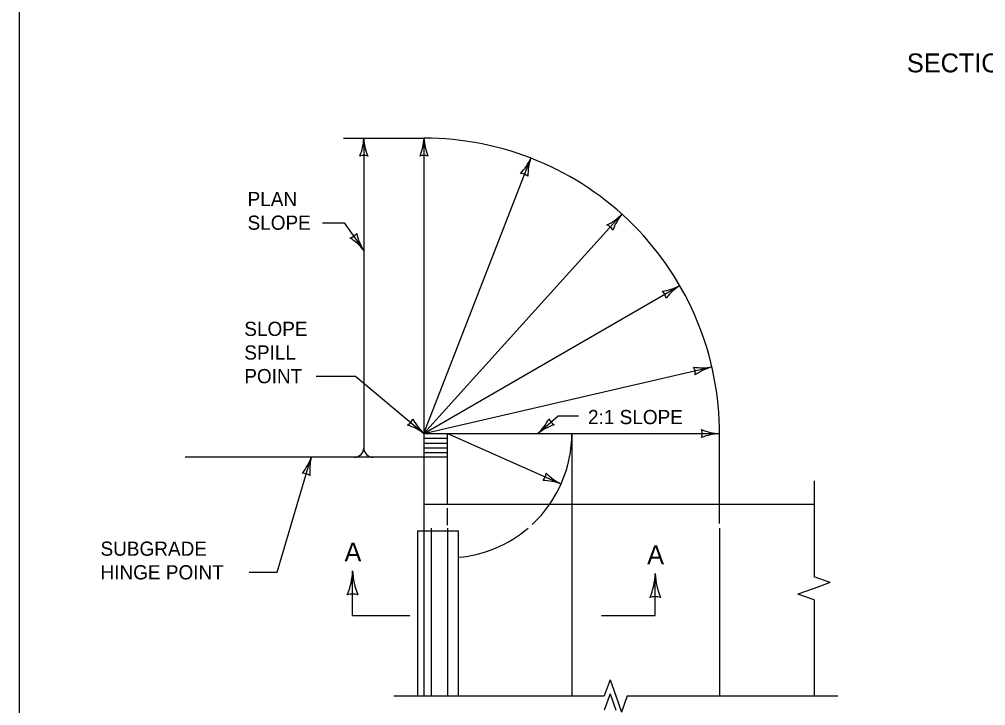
# Model space of a CAD drawing. Extents: x 49991.4 to 50021, y 49987.6 to 50011.4.
# Drawn here: x 50000.336 to 50004.423, y 50005.456 to 50008.359 of the extents above; entities that cross this region are included whole.
import ezdxf

# ---------------------------------------------------------------- set-up
doc = ezdxf.new("R2010")
doc.units = 0
for name, color, linetype in [('Level 1', 7, 'Continuous'), ('Level 2', 7, 'Continuous'), ('Level 3', 7, 'Continuous'), ('Level 4', 7, 'Continuous'), ('Level 6', 7, 'Continuous')]:
    doc.layers.add(name, color=color, linetype=linetype)

msp = doc.modelspace()

# ---------------------------------------------------------------- linework, layer by layer
at = {"layer": 'Level 1'}
for p, q in [((50001.7071, 50007.857), (50002.0471, 50007.857)), ((50002.0471, 50006.607), (50002.1471, 50006.607)), ((50002.0471, 50006.607), (50002.0471, 50005.497)), ((50002.0471, 50006.587), (50002.1471, 50006.587)), ((50002.1471, 50006.307), (50002.1471, 50006.607)), ((50002.6722, 50006.607), (50002.6721, 50006.307)), ((50003.2971, 50006.307), (50003.2971, 50006.607)), ((50002.0471, 50006.567), (50002.1471, 50006.567)), ((50002.0471, 50006.547), (50002.1471, 50006.547)), ((50002.0471, 50006.527), (50002.1471, 50006.527)), ((50002.1471, 50006.507), (50001.0369, 50006.507)), ((50003.6971, 50006.307), (50002.0471, 50006.307)), ((50002.0786, 50005.497), (50002.0786, 50006.207))]:
    msp.add_line(p, q, dxfattribs=at)
msp.add_lwpolyline([(50008.6146, 50011.2628), (50000.3356, 50011.2628), (50000.3356, 50000.0624), (50008.6146, 50000.0624)], close=True, dxfattribs=at)
for centre, radius, start, end in [((50002.0471, 50006.607), 1.25, 359.8042, 90), ((50002.1471, 50006.607), 0.5251, 325.1554, 0)]:
    msp.add_arc(centre, radius, start, end, dxfattribs=at)
at = {"layer": 'Level 3'}
for p, q in [((50001.7924, 50007.857), (50001.7924, 50006.547)), ((50002.0471, 50007.857), (50002.0471, 50006.607)), ((50002.0471, 50006.607), (50002.4987, 50007.7726)), ((50002.0471, 50006.607), (50002.8844, 50007.5352)), ((50001.6185, 50007.4992), (50001.7097, 50007.4992)), ((50001.7097, 50007.4992), (50001.7924, 50007.3818)), ((50002.0471, 50006.607), (50003.1291, 50007.2329)), ((50002.0471, 50006.607), (50003.2649, 50006.889)), ((50001.5909, 50006.8501), (50001.7568, 50006.8501)), ((50001.7568, 50006.8501), (50002.0471, 50006.607)), ((50002.5292, 50006.607), (50002.6141, 50006.6816)), ((50002.6141, 50006.6816), (50002.7007, 50006.6816)), ((50002.1471, 50006.607), (50003.2971, 50006.607)), ((50002.1471, 50006.607), (50002.626, 50006.3939)), ((50001.4267, 50006.0202), (50001.5702, 50006.507)), ((50001.3083, 50006.0202), (50001.4267, 50006.0202))]:
    msp.add_line(p, q, dxfattribs=at)
for centre, radius, start, end in [((50001.5703, 50007.8662), 0.2223, 337.456, 357.6395), ((50002.0251, 50007.8685), 0.233, 182.8273, 202.0772), ((50001.825, 50007.8662), 0.2223, 337.456, 357.6395), ((50002.2798, 50007.8685), 0.233, 182.8273, 202.0772), ((50001.7924, 50007.7288), 0.0548, 72.1388, 107.8612), ((50002.0471, 50007.7288), 0.0548, 72.1388, 107.8612), ((50002.2949, 50007.8614), 0.2223, 316.2777, 336.4612), ((50002.7198, 50007.6993), 0.233, 161.649, 180.8988), ((50002.4524, 50007.6531), 0.0548, 50.9605, 86.6828), ((50002.7256, 50007.6908), 0.2223, 295.4034, 315.5869), ((50003.0649, 50007.3879), 0.233, 140.7747, 160.0245), ((50002.7985, 50007.44), 0.0548, 30.0862, 65.8086), ((50001.7186, 50007.4867), 0.0548, 287.2981, 323.0205), ((50001.6088, 50007.2384), 0.233, 37.9866, 57.2364), ((50001.9793, 50007.5023), 0.2223, 192.6153, 212.7988), ((50003.0258, 50007.4298), 0.2223, 277.5039, 297.6874), ((50003.2556, 50007.0373), 0.233, 122.8752, 142.1251), ((50003.0181, 50007.1687), 0.0548, 12.1867, 47.9091), ((50003.2237, 50007.1075), 0.2223, 260.4939, 280.6774), ((50003.14, 50006.8601), 0.0548, 355.1767, 30.8991), ((50003.3286, 50006.6649), 0.233, 105.8652, 125.1151), ((50001.9488, 50006.6893), 0.0548, 302.196, 337.9184), ((50002.1967, 50006.7715), 0.2223, 207.5132, 227.6967), ((50002.367, 50006.7743), 0.233, 314.1325, 333.3823), ((50002.6255, 50006.6917), 0.0548, 203.444, 239.1663), ((50001.9065, 50006.4212), 0.233, 52.8845, 72.1344), ((50002.6689, 50006.4341), 0.2223, 108.7612, 128.9447), ((50003.3063, 50006.8292), 0.2223, 247.456, 267.6395), ((50003.1689, 50006.607), 0.0548, 342.1388, 17.8612), ((50003.3086, 50006.3743), 0.233, 92.8273, 112.0772), ((50001.7524, 50006.547), 0.04, 270, 0), ((50001.8324, 50006.547), 0.04, 180, 270), ((50001.3503, 50006.5839), 0.233, 321.4954, 340.7453), ((50001.7859, 50006.453), 0.2223, 165.9331, 186.1166), ((50001.534, 50006.3841), 0.0548, 55.7114, 91.4338), ((50002.5097, 50006.4457), 0.0548, 318.1508, 353.8732), ((50002.5427, 50006.1763), 0.233, 68.8393, 88.0891), ((50002.7255, 50006.5928), 0.2223, 223.468, 243.6515), ((50001.4491, 50006.0385), 0.2964, 337.456, 357.6395), ((50002.0556, 50006.0417), 0.3107, 182.8273, 202.0772), ((50002.7291, 50006.0268), 0.2964, 337.456, 357.6395), ((50003.3356, 50006.03), 0.3107, 182.8273, 202.0772), ((50001.7453, 50005.8554), 0.073, 72.1388, 107.8612), ((50003.0253, 50005.8437), 0.073, 72.1388, 107.8612)]:
    msp.add_arc(centre, radius, start, end, dxfattribs=at)
at = {"layer": 'Level 4'}
for p, q in [((50002.1471, 50006.2203), (50002.1471, 50006.2917)), ((50002.6721, 50006.307), (50002.6721, 50005.497)), ((50003.2971, 50006.2273), (50003.2971, 50006.307)), ((50002.1471, 50006.207), (50002.1471, 50005.497)), ((50003.2971, 50006.207), (50003.2971, 50005.497)), ((50002.0198, 50006.1958), (50002.0198, 50005.497)), ((50002.0198, 50006.1958), (50002.1933, 50006.1958)), ((50002.1933, 50005.497), (50002.1933, 50006.1958))]:
    msp.add_line(p, q, dxfattribs=at)
for start, end in [(312.8418, 325.1554), (275.0479, 310.3608)]:
    msp.add_arc((50002.1471, 50006.607), 0.5251, start, end, dxfattribs=at)
at = {"layer": 'Level 6'}
for p, q in [((50003.6971, 50006.407), (50003.6971, 50006.001)), ((50001.7453, 50005.8372), (50001.7453, 50006.0263)), ((50003.0253, 50005.8372), (50003.0253, 50006.0146)), ((50003.7656, 50005.9767), (50003.6971, 50006.001)), ((50003.7656, 50005.9767), (50003.6971, 50005.9524)), ((50003.6971, 50005.9524), (50003.6286, 50005.9281)), ((50003.6971, 50005.9038), (50003.6286, 50005.9281)), ((50003.6971, 50005.9038), (50003.6971, 50005.497)), ((50001.7453, 50005.8372), (50001.9866, 50005.8372)), ((50002.798, 50005.8372), (50003.0253, 50005.8372)), ((50002.8341, 50005.5655), (50002.8098, 50005.497)), ((50002.8341, 50005.5655), (50002.8584, 50005.497)), ((50002.8341, 50005.5055), (50002.8098, 50005.437)), ((50002.8341, 50005.5055), (50002.8584, 50005.437)), ((50001.9198, 50005.497), (50002.8098, 50005.497)), ((50002.8584, 50005.497), (50002.8827, 50005.4285)), ((50002.907, 50005.497), (50002.8827, 50005.4285)), ((50002.907, 50005.497), (50003.7971, 50005.497))]:
    msp.add_line(p, q, dxfattribs=at)

# ---------------------------------------------------------------- texts
at = {"layer": 'Level 2'}
for s, height, p in [('SECTION A-A', 0.08, (50004.0895, 50008.1351)), ('PLAN', 0.06, (50001.3009, 50007.5692)), ('SLOPE', 0.06, (50001.3009, 50007.4692)), ('SLOPE', 0.06, (50001.2871, 50007.0201)), ('SPILL ', 0.06, (50001.2871, 50006.9201)), ('POINT', 0.06, (50001.2871, 50006.8201)), ('2:1 SLOPE', 0.06, (50002.7407, 50006.647)), ('SUBGRADE ', 0.06, (50000.6789, 50006.0902)), ('A', 0.0799, (50001.711, 50006.0663)), ('A', 0.0799, (50002.991, 50006.0546)), ('HINGE POINT', 0.06, (50000.6789, 50005.9902))]:
    msp.add_text(s, height=height, dxfattribs=at).set_placement(p)

doc.saveas('drawing.dxf')
